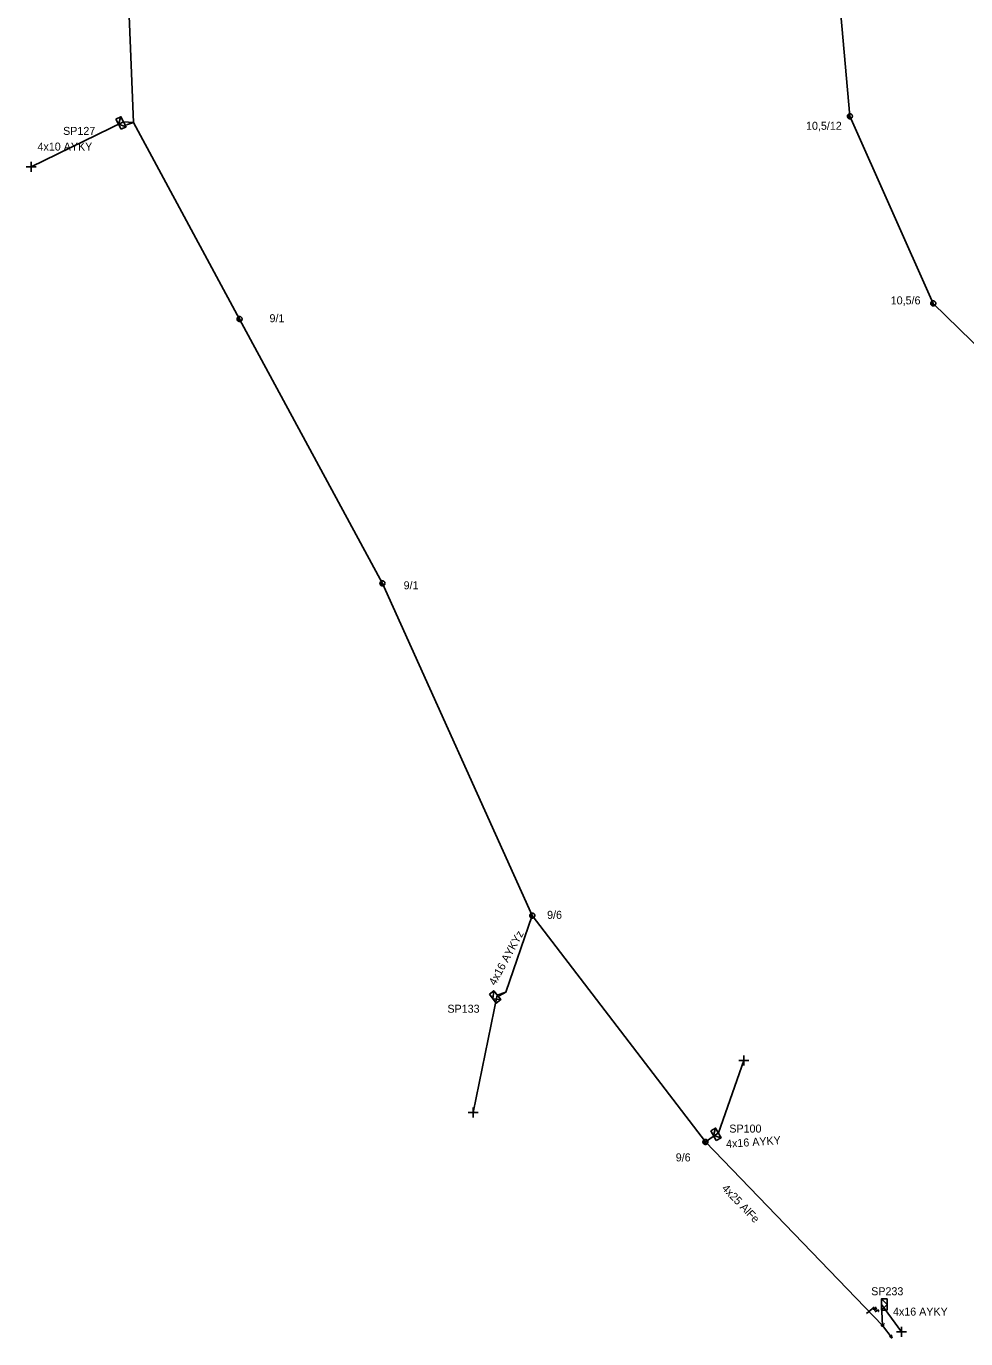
# Model space of a CAD drawing. Extents: x -717562 to -713845, y -1151196 to -1143903.
# Drawn here: x -714279.3 to -714161.9, y -1146660.9 to -1146496.9 of the extents above; entities that cross this region are included whole.
import ezdxf

# ---------------------------------------------------------------- set-up
doc = ezdxf.new("R2010")
doc.units = 0
for name, color, linetype in [('Vrstva 1', 7, 'Continuous'), ('Vrstva 12', 7, 'Continuous'), ('Vrstva 13', 7, 'Continuous'), ('Vrstva 15', 7, 'Continuous'), ('Vrstva 18', 7, 'Continuous'), ('Vrstva 2', 7, 'Continuous'), ('Vrstva 31', 7, 'Continuous'), ('Vrstva 33', 7, 'Continuous'), ('Vrstva 34', 7, 'Continuous'), ('Vrstva 50', 7, 'Continuous'), ('Vrstva 52', 7, 'Continuous'), ('Vrstva 54', 7, 'Continuous'), ('Vrstva 55', 7, 'Continuous'), ('Vrstva 59', 7, 'Continuous'), ('Vrstva 9', 7, 'Continuous')]:
    doc.layers.add(name, color=color, linetype=linetype)

# ---------------------------------------------------------------- blocks, each defined once
blk = doc.blocks.new('NN440')
at = {"layer": 'Vrstva 2'}
for points in [[(0.63, 0), (0.63, 0.06), (0.62, 0.13), (0.6, 0.19), (0.58, 0.25), (0.55, 0.31), (0.51, 0.37), (0.47, 0.42), (0.42, 0.46), (0.37, 0.51), (0.32, 0.54), (0.26, 0.57), (0.2, 0.59), (0.13, 0.61), (0.07, 0.62), (0, 0.63), (-0.06, 0.62), (-0.13, 0.61), (-0.19, 0.59), (-0.26, 0.57), (-0.31, 0.54), (-0.37, 0.51), (-0.42, 0.46), (-0.47, 0.42), (-0.51, 0.37), (-0.54, 0.31), (-0.57, 0.25), (-0.6, 0.19), (-0.62, 0.13), (-0.63, 0.06), (-0.63, 0), (-0.63, -0.07), (-0.62, -0.14), (-0.6, -0.2), (-0.57, -0.26), (-0.54, -0.32), (-0.51, -0.37), (-0.47, -0.43), (-0.42, -0.47), (-0.37, -0.51), (-0.31, -0.55), (-0.26, -0.58), (-0.19, -0.6), (-0.13, -0.62), (-0.06, -0.63), (0, -0.63), (0.07, -0.63), (0.13, -0.62), (0.2, -0.6), (0.26, -0.58), (0.32, -0.55), (0.37, -0.51), (0.42, -0.47), (0.47, -0.43), (0.51, -0.37), (0.55, -0.32), (0.58, -0.26), (0.6, -0.2), (0.62, -0.14), (0.63, -0.07), (0.63, 0)], [(-0.63, 0), (0.63, 0)], [(-0.6, -0.18), (0.57, -0.18)], [(-0.51, -0.32), (0.5, -0.32)], [(-0.37, -0.47), (0.35, -0.47)]]:
    blk.add_lwpolyline(points, dxfattribs=at)
blk = doc.blocks.new('NN560')
at = {"layer": 'Vrstva 2'}
for points in [[(2, 0), (1.59, 0.14)], [(0, 0), (2, 0)], [(2, 0), (1.59, -0.13)]]:
    blk.add_lwpolyline(points, dxfattribs=at)
blk = doc.blocks.new('NN840')
at = {"layer": 'Vrstva 15'}
for points in [[(0, 0.62), (0, -0.63)], [(-0.75, -0.71), (-0.75, -0.66)], [(-0.73, -0.76), (-0.75, -0.71)], [(-0.66, -0.8), (-0.73, -0.76)], [(-0.63, -0.8), (-0.66, -0.8)], [(-0.56, -0.76), (-0.63, -0.8)], [(-0.54, -0.71), (-0.56, -0.76)], [(-0.54, -0.38), (-0.54, -0.71)], [(-0.33, -0.38), (-0.33, -0.8)], [(-0.33, -0.64), (-0.13, -0.38)], [(-0.26, -0.56), (-0.09, -0.8)]]:
    blk.add_lwpolyline(points, dxfattribs=at)
blk = doc.blocks.new('NN800')
at = {"layer": 'Vrstva 1'}
for points in [[(-0.44, 0.44), (0.44, -0.44)], [(-0.44, -0.44), (0.44, 0.44)]]:
    blk.add_lwpolyline(points, dxfattribs=at)
blk = doc.blocks.new('NN630')
at = {"layer": 'Vrstva 9'}
for points in [[(0, -0.7), (-0.7, 0)], [(-0.7, -0.7), (-0.7, 0), (0.7, 0), (0.7, -0.7)], [(-0.7, -0.7), (0.7, -0.7)], [(0, -0.7), (0.7, 0)]]:
    blk.add_lwpolyline(points, dxfattribs=at)
blk = doc.blocks.new('NN500')
at = {"layer": 'Vrstva 2'}
for points in [[(0, -0.24), (0.02, -0.23), (0.05, -0.23), (0.07, -0.22), (0.09, -0.22), (0.12, -0.2), (0.14, -0.19), (0.16, -0.18), (0.17, -0.16), (0.19, -0.14), (0.2, -0.12), (0.21, -0.1), (0.22, -0.07), (0.23, -0.05), (0.23, -0.02), (0.23, 0), (0.23, 0.02), (0.23, 0.05), (0.22, 0.07), (0.21, 0.1), (0.2, 0.12), (0.19, 0.14), (0.17, 0.16), (0.16, 0.17), (0.14, 0.19), (0.12, 0.2), (0.09, 0.21), (0.07, 0.22), (0.05, 0.23), (0.02, 0.23), (0, 0.23), (-0.03, 0.23), (-0.05, 0.23), (-0.07, 0.22), (-0.1, 0.21), (-0.12, 0.2), (-0.14, 0.19), (-0.16, 0.17), (-0.18, 0.16), (-0.19, 0.14), (-0.2, 0.12), (-0.22, 0.1), (-0.22, 0.07), (-0.23, 0.05), (-0.23, 0.02), (-0.24, 0), (-0.23, -0.02), (-0.23, -0.05), (-0.22, -0.07), (-0.22, -0.1), (-0.2, -0.12), (-0.19, -0.14), (-0.18, -0.16), (-0.16, -0.18), (-0.14, -0.19), (-0.12, -0.2), (-0.1, -0.22), (-0.07, -0.22), (-0.05, -0.23), (-0.03, -0.23), (0, -0.24)], [(0, -0.24), (0.02, -0.23), (0.05, -0.23), (0.07, -0.22), (0.09, -0.22), (0.12, -0.2), (0.14, -0.19), (0.16, -0.18), (0.17, -0.16), (0.19, -0.14), (0.2, -0.12), (0.21, -0.1), (0.22, -0.07), (0.23, -0.05), (0.23, -0.02), (0.23, 0), (0.23, 0.02), (0.23, 0.05), (0.22, 0.07), (0.21, 0.1), (0.2, 0.12), (0.19, 0.14), (0.17, 0.16), (0.16, 0.17), (0.14, 0.19), (0.12, 0.2), (0.09, 0.21), (0.07, 0.22), (0.05, 0.23), (0.02, 0.23), (0, 0.23), (-0.03, 0.23), (-0.05, 0.23), (-0.07, 0.22), (-0.1, 0.21), (-0.12, 0.2), (-0.14, 0.19), (-0.16, 0.17), (-0.18, 0.16), (-0.19, 0.14), (-0.2, 0.12), (-0.22, 0.1), (-0.22, 0.07), (-0.23, 0.05), (-0.23, 0.02), (-0.24, 0), (-0.23, -0.02), (-0.23, -0.05), (-0.22, -0.07), (-0.22, -0.1), (-0.2, -0.12), (-0.19, -0.14), (-0.18, -0.16), (-0.16, -0.18), (-0.14, -0.19), (-0.12, -0.2), (-0.1, -0.22), (-0.07, -0.22), (-0.05, -0.23), (-0.03, -0.23), (0, -0.24)], [(0, -0.21), (0.02, -0.2), (0.04, -0.2), (0.06, -0.2), (0.08, -0.19), (0.1, -0.18), (0.12, -0.17), (0.14, -0.15), (0.15, -0.14), (0.16, -0.12), (0.18, -0.1), (0.19, -0.08), (0.19, -0.06), (0.2, -0.04), (0.2, -0.02), (0.2, 0), (0.2, 0.02), (0.2, 0.04), (0.19, 0.06), (0.19, 0.08), (0.18, 0.1), (0.16, 0.12), (0.15, 0.14), (0.14, 0.15), (0.12, 0.17), (0.1, 0.18), (0.08, 0.19), (0.06, 0.19), (0.04, 0.2), (0.02, 0.2), (0, 0.2), (-0.02, 0.2), (-0.04, 0.2), (-0.06, 0.19), (-0.08, 0.19), (-0.1, 0.18), (-0.12, 0.17), (-0.14, 0.15), (-0.15, 0.14), (-0.17, 0.12), (-0.18, 0.1), (-0.19, 0.08), (-0.2, 0.06), (-0.2, 0.04), (-0.21, 0.02), (-0.21, 0), (-0.21, -0.02), (-0.2, -0.04), (-0.2, -0.06), (-0.19, -0.08), (-0.18, -0.1), (-0.17, -0.12), (-0.15, -0.14), (-0.14, -0.15), (-0.12, -0.17), (-0.1, -0.18), (-0.08, -0.19), (-0.06, -0.2), (-0.04, -0.2), (-0.02, -0.2), (0, -0.21)], [(0, -0.18), (0.02, -0.18), (0.04, -0.17), (0.05, -0.17), (0.07, -0.16), (0.09, -0.15), (0.1, -0.14), (0.12, -0.13), (0.13, -0.12), (0.14, -0.1), (0.15, -0.09), (0.16, -0.07), (0.17, -0.05), (0.17, -0.04), (0.17, -0.02), (0.17, 0), (0.17, 0.02), (0.17, 0.04), (0.17, 0.05), (0.16, 0.07), (0.15, 0.09), (0.14, 0.1), (0.13, 0.12), (0.12, 0.13), (0.1, 0.14), (0.09, 0.15), (0.07, 0.16), (0.05, 0.17), (0.04, 0.17), (0.02, 0.17), (0, 0.18), (-0.02, 0.17), (-0.04, 0.17), (-0.06, 0.17), (-0.07, 0.16), (-0.09, 0.15), (-0.1, 0.14), (-0.12, 0.13), (-0.13, 0.12), (-0.14, 0.1), (-0.15, 0.09), (-0.16, 0.07), (-0.17, 0.05), (-0.17, 0.04), (-0.18, 0.02), (-0.18, 0), (-0.18, -0.02), (-0.17, -0.04), (-0.17, -0.05), (-0.16, -0.07), (-0.15, -0.09), (-0.14, -0.1), (-0.13, -0.12), (-0.12, -0.13), (-0.1, -0.14), (-0.09, -0.15), (-0.07, -0.16), (-0.06, -0.17), (-0.04, -0.17), (-0.02, -0.18), (0, -0.18)], [(0, -0.15), (0.01, -0.15), (0.03, -0.14), (0.04, -0.14), (0.06, -0.13), (0.07, -0.13), (0.08, -0.12), (0.1, -0.11), (0.11, -0.1), (0.12, -0.09), (0.13, -0.07), (0.13, -0.06), (0.14, -0.05), (0.14, -0.03), (0.14, -0.02), (0.14, 0), (0.14, 0.01), (0.14, 0.03), (0.14, 0.04), (0.13, 0.06), (0.13, 0.07), (0.12, 0.09), (0.11, 0.1), (0.1, 0.11), (0.08, 0.12), (0.07, 0.13), (0.06, 0.13), (0.04, 0.14), (0.03, 0.14), (0.01, 0.14), (0, 0.15), (-0.02, 0.14), (-0.03, 0.14), (-0.05, 0.14), (-0.06, 0.13), (-0.07, 0.13), (-0.09, 0.12), (-0.1, 0.11), (-0.11, 0.1), (-0.12, 0.09), (-0.13, 0.07), (-0.13, 0.06), (-0.14, 0.04), (-0.14, 0.03), (-0.15, 0.01), (-0.15, 0), (-0.15, -0.02), (-0.14, -0.03), (-0.14, -0.05), (-0.13, -0.06), (-0.13, -0.07), (-0.12, -0.09), (-0.11, -0.1), (-0.1, -0.11), (-0.09, -0.12), (-0.07, -0.13), (-0.06, -0.13), (-0.05, -0.14), (-0.03, -0.14), (-0.02, -0.15), (0, -0.15)], [(0, -0.12), (0.01, -0.12), (0.02, -0.11), (0.03, -0.11), (0.05, -0.11), (0.06, -0.1), (0.07, -0.09), (0.08, -0.09), (0.09, -0.08), (0.09, -0.07), (0.1, -0.06), (0.11, -0.05), (0.11, -0.04), (0.11, -0.02), (0.11, -0.01), (0.12, 0), (0.11, 0.01), (0.11, 0.02), (0.11, 0.04), (0.11, 0.05), (0.1, 0.06), (0.09, 0.07), (0.09, 0.08), (0.08, 0.09), (0.07, 0.09), (0.06, 0.1), (0.05, 0.11), (0.03, 0.11), (0.02, 0.11), (0.01, 0.12), (0, 0.12), (-0.01, 0.12), (-0.03, 0.11), (-0.04, 0.11), (-0.05, 0.11), (-0.06, 0.1), (-0.07, 0.09), (-0.08, 0.09), (-0.09, 0.08), (-0.1, 0.07), (-0.1, 0.06), (-0.11, 0.05), (-0.11, 0.04), (-0.12, 0.02), (-0.12, 0.01), (-0.12, 0), (-0.12, -0.01), (-0.12, -0.02), (-0.11, -0.04), (-0.11, -0.05), (-0.1, -0.06), (-0.1, -0.07), (-0.09, -0.08), (-0.08, -0.09), (-0.07, -0.09), (-0.06, -0.1), (-0.05, -0.11), (-0.04, -0.11), (-0.03, -0.11), (-0.01, -0.12), (0, -0.12)], [(0, -0.09), (0.01, -0.09), (0.02, -0.09), (0.03, -0.08), (0.03, -0.08), (0.04, -0.08), (0.05, -0.07), (0.06, -0.07), (0.06, -0.06), (0.07, -0.05), (0.07, -0.04), (0.08, -0.04), (0.08, -0.03), (0.08, -0.02), (0.09, -0.01), (0.09, 0), (0.09, 0.01), (0.08, 0.02), (0.08, 0.03), (0.08, 0.03), (0.07, 0.04), (0.07, 0.05), (0.06, 0.06), (0.06, 0.06), (0.05, 0.07), (0.04, 0.07), (0.03, 0.08), (0.03, 0.08), (0.02, 0.08), (0.01, 0.09), (0, 0.09), (-0.01, 0.09), (-0.02, 0.08), (-0.03, 0.08), (-0.04, 0.08), (-0.04, 0.07), (-0.05, 0.07), (-0.06, 0.06), (-0.07, 0.06), (-0.07, 0.05), (-0.08, 0.04), (-0.08, 0.03), (-0.08, 0.03), (-0.09, 0.02), (-0.09, 0.01), (-0.09, 0), (-0.09, -0.01), (-0.09, -0.02), (-0.08, -0.03), (-0.08, -0.04), (-0.08, -0.04), (-0.07, -0.05), (-0.07, -0.06), (-0.06, -0.07), (-0.05, -0.07), (-0.04, -0.08), (-0.04, -0.08), (-0.03, -0.08), (-0.02, -0.09), (-0.01, -0.09), (0, -0.09)], [(0, -0.06), (0, -0.06), (0.01, -0.06), (0.02, -0.05), (0.02, -0.05), (0.03, -0.05), (0.03, -0.05), (0.04, -0.04), (0.04, -0.04), (0.05, -0.03), (0.05, -0.03), (0.05, -0.02), (0.05, -0.02), (0.05, -0.01), (0.06, -0.01), (0.06, 0), (0.06, 0.01), (0.05, 0.01), (0.05, 0.02), (0.05, 0.02), (0.05, 0.03), (0.05, 0.03), (0.04, 0.04), (0.04, 0.04), (0.03, 0.05), (0.03, 0.05), (0.02, 0.05), (0.02, 0.05), (0.01, 0.06), (0, 0.06), (0, 0.06), (-0.01, 0.06), (-0.01, 0.06), (-0.02, 0.05), (-0.02, 0.05), (-0.03, 0.05), (-0.03, 0.05), (-0.04, 0.04), (-0.04, 0.04), (-0.05, 0.03), (-0.05, 0.03), (-0.05, 0.02), (-0.06, 0.02), (-0.06, 0.01), (-0.06, 0.01), (-0.06, 0), (-0.06, -0.01), (-0.06, -0.01), (-0.06, -0.02), (-0.05, -0.02), (-0.05, -0.03), (-0.05, -0.03), (-0.04, -0.04), (-0.04, -0.04), (-0.03, -0.05), (-0.03, -0.05), (-0.02, -0.05), (-0.02, -0.05), (-0.01, -0.06), (-0.01, -0.06), (0, -0.06)], [(0, -0.03), (0, -0.03), (0, -0.03), (0.01, -0.03), (0.01, -0.03), (0.01, -0.02), (0.02, -0.02), (0.02, -0.02), (0.02, -0.02), (0.02, -0.02), (0.02, -0.01), (0.02, -0.01), (0.03, -0.01), (0.03, -0.01), (0.03, 0), (0.03, 0), (0.03, 0), (0.03, 0.01), (0.03, 0.01), (0.02, 0.01), (0.02, 0.01), (0.02, 0.02), (0.02, 0.02), (0.02, 0.02), (0.02, 0.02), (0.01, 0.02), (0.01, 0.02), (0.01, 0.03), (0, 0.03), (0, 0.03), (0, 0.03), (0, 0.03), (-0.01, 0.03), (-0.01, 0.03), (-0.01, 0.02), (-0.02, 0.02), (-0.02, 0.02), (-0.02, 0.02), (-0.02, 0.02), (-0.02, 0.02), (-0.03, 0.01), (-0.03, 0.01), (-0.03, 0.01), (-0.03, 0.01), (-0.03, 0), (-0.03, 0), (-0.03, 0), (-0.03, -0.01), (-0.03, -0.01), (-0.03, -0.01), (-0.03, -0.01), (-0.02, -0.02), (-0.02, -0.02), (-0.02, -0.02), (-0.02, -0.02), (-0.02, -0.02), (-0.01, -0.03), (-0.01, -0.03), (-0.01, -0.03), (0, -0.03), (0, -0.03)], [(0.23, 0), (0.7, 0)]]:
    blk.add_lwpolyline(points, dxfattribs=at)
blk = doc.blocks.new('NN510')
at = {"layer": 'Vrstva 2'}
blk.add_lwpolyline([(0, 0), (0, 0.94)], dxfattribs=at)

msp = doc.modelspace()

# ---------------------------------------------------------------- linework, layer by layer
at = {"layer": 'Vrstva 1'}
for points in [[(-714244.01, -1146351.87), (-714258.08, -1146379.09), (-714272.25, -1146406.38), (-714268.89, -1146438.43), (-714267.37, -1146471.99), (-714265.86, -1146508.97), (-714252.61, -1146533.5), (-714234.76, -1146566.52), (-714216.05, -1146608.02), (-714194.42, -1146636.29), (-714172.31, -1146659.2)], [(-714178.78, -1146406.19), (-714181.73, -1146443.01), (-714181.42, -1146447.42), (-714179.69, -1146470.98), (-714176.38, -1146508.17)]]:
    msp.add_lwpolyline(points, dxfattribs=at)
at = {"layer": 'Vrstva 50'}
msp.add_lwpolyline([(-714176.38, -1146508.17), (-714165.97, -1146531.55), (-714141.83, -1146555.08)], dxfattribs=at)
at = {"layer": 'Vrstva 52'}
for points in [[(-714265.86, -1146508.97), (-714267.11, -1146508.85)], [(-714194.42, -1146636.29), (-714192.81, -1146635.16)], [(-714172.31, -1146659.2), (-714172.44, -1146656.6)]]:
    msp.add_lwpolyline(points, dxfattribs=at)
at = {"layer": 'Vrstva 54'}
msp.add_lwpolyline([(-714216.05, -1146608.02), (-714219.37, -1146617.59), (-714220.43, -1146617.96)], dxfattribs=at)
at = {"layer": 'Vrstva 59'}
for points in [[(-714267.11, -1146508.85), (-714278.63, -1146514.5)], [(-714220.43, -1146617.96), (-714223.44, -1146632.63)], [(-714192.81, -1146635.16), (-714189.63, -1146626.13)], [(-714172.44, -1146656.6), (-714169.94, -1146660)]]:
    msp.add_lwpolyline(points, dxfattribs=at)

# ---------------------------------------------------------------- block references
at = {"layer": 'Vrstva 13'}
for name, p, rotation in [('NN510', (-714265.86, -1146508.97), 107.89808892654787), ('NN510', (-714219.37, -1146617.59), 119.13194989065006), ('NN560', (-714172.31, -1146659.2), -52.87253174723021)]:
    msp.add_blockref(name, p, dxfattribs=dict(at, rotation=rotation))
for name, p, xscale, yscale, rotation in [('NN440', (-714176.38, -1146508.17), 0.5, 0.5000000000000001, -84.91393833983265), ('NN440', (-714165.97, -1146531.55), 0.5000000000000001, 0.4999999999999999, -65.99886825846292), ('NN440', (-714252.61, -1146533.5), 0.5, 0.49999999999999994, -61.611091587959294), ('NN440', (-714234.76, -1146566.52), 0.5, 0.5, -61.61109171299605), ('NN440', (-714216.05, -1146608.02), 0.5, 0.5, -61.61109171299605), ('NN440', (-714194.42, -1146636.29), 0.49999999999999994, 0.5, -53.35041114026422), ('NN500', (-714172.31, -1146659.2), 0.5, 0.5, 39.28000009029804)]:
    msp.add_blockref(name, p, dxfattribs=dict(at, xscale=xscale, yscale=yscale, rotation=rotation))
at = {"layer": 'Vrstva 18', "rotation": 129.2799500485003}
msp.add_blockref('NN840', (-714173.84, -1146657.32), dxfattribs=at)
at = {"layer": 'Vrstva 31'}
for p, rotation in [((-714267.11, -1146508.85), -63.178019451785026), ((-714220.43, -1146617.96), -51.80224435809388), ((-714192.81, -1146635.16), -60.98728049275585), ((-714172.44, -1146656.6), 90)]:
    msp.add_blockref('NN630', p, dxfattribs=dict(at, rotation=rotation))
at = {"layer": 'Vrstva 34'}
for p, rotation in [((-714278.63, -1146514.5), 45), ((-714189.63, -1146626.13), 45), ((-714223.44, -1146632.63), 44.99999995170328), ((-714169.94, -1146660), 44.99999995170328)]:
    msp.add_blockref('NN800', p, dxfattribs=dict(at, rotation=rotation))

# ---------------------------------------------------------------- texts
at = {"layer": 'Vrstva 12'}
for s, p in [('10,5/12', (-714181.86, -1146509.86)), ('10,5/6', (-714171.28, -1146531.67)), ('9/1', (-714248.87, -1146533.9)), ('9/1', (-714232.12, -1146567.26)), ('9/6', (-714214.2, -1146608.42)), ('9/6', (-714198.13, -1146638.72))]:
    msp.add_text(s, height=1, dxfattribs=at).set_placement(p)
at = {"layer": 'Vrstva 2'}
msp.add_text('4x25 AlFe', height=1, rotation=313.983, dxfattribs=at).set_placement((-714192.46, -1146642.16))
at = {"layer": 'Vrstva 33'}
for s, p in [('SP127', (-714274.65, -1146510.5)), ('SP133', (-714226.65, -1146620.15)), ('SP100', (-714191.44, -1146635.12)), ('SP233', (-714173.72, -1146655.44))]:
    msp.add_text(s, height=1, dxfattribs=at).set_placement(p)
at = {"layer": 'Vrstva 54'}
for s, p in [('4x10 AYKY', (-714277.85, -1146512.46)), ('4x16 AYKY', (-714171, -1146657.98))]:
    msp.add_text(s, height=1, dxfattribs=at).set_placement(p)
msp.add_text('4x16 AYKY', height=1, rotation=3.991, dxfattribs=at).set_placement((-714191.81, -1146637.03))
at = {"layer": 'Vrstva 55'}
msp.add_text('4x16 AYKYz', height=1, rotation=61.303, dxfattribs=at).set_placement((-714220.68, -1146616.82))

doc.saveas('drawing.dxf')
